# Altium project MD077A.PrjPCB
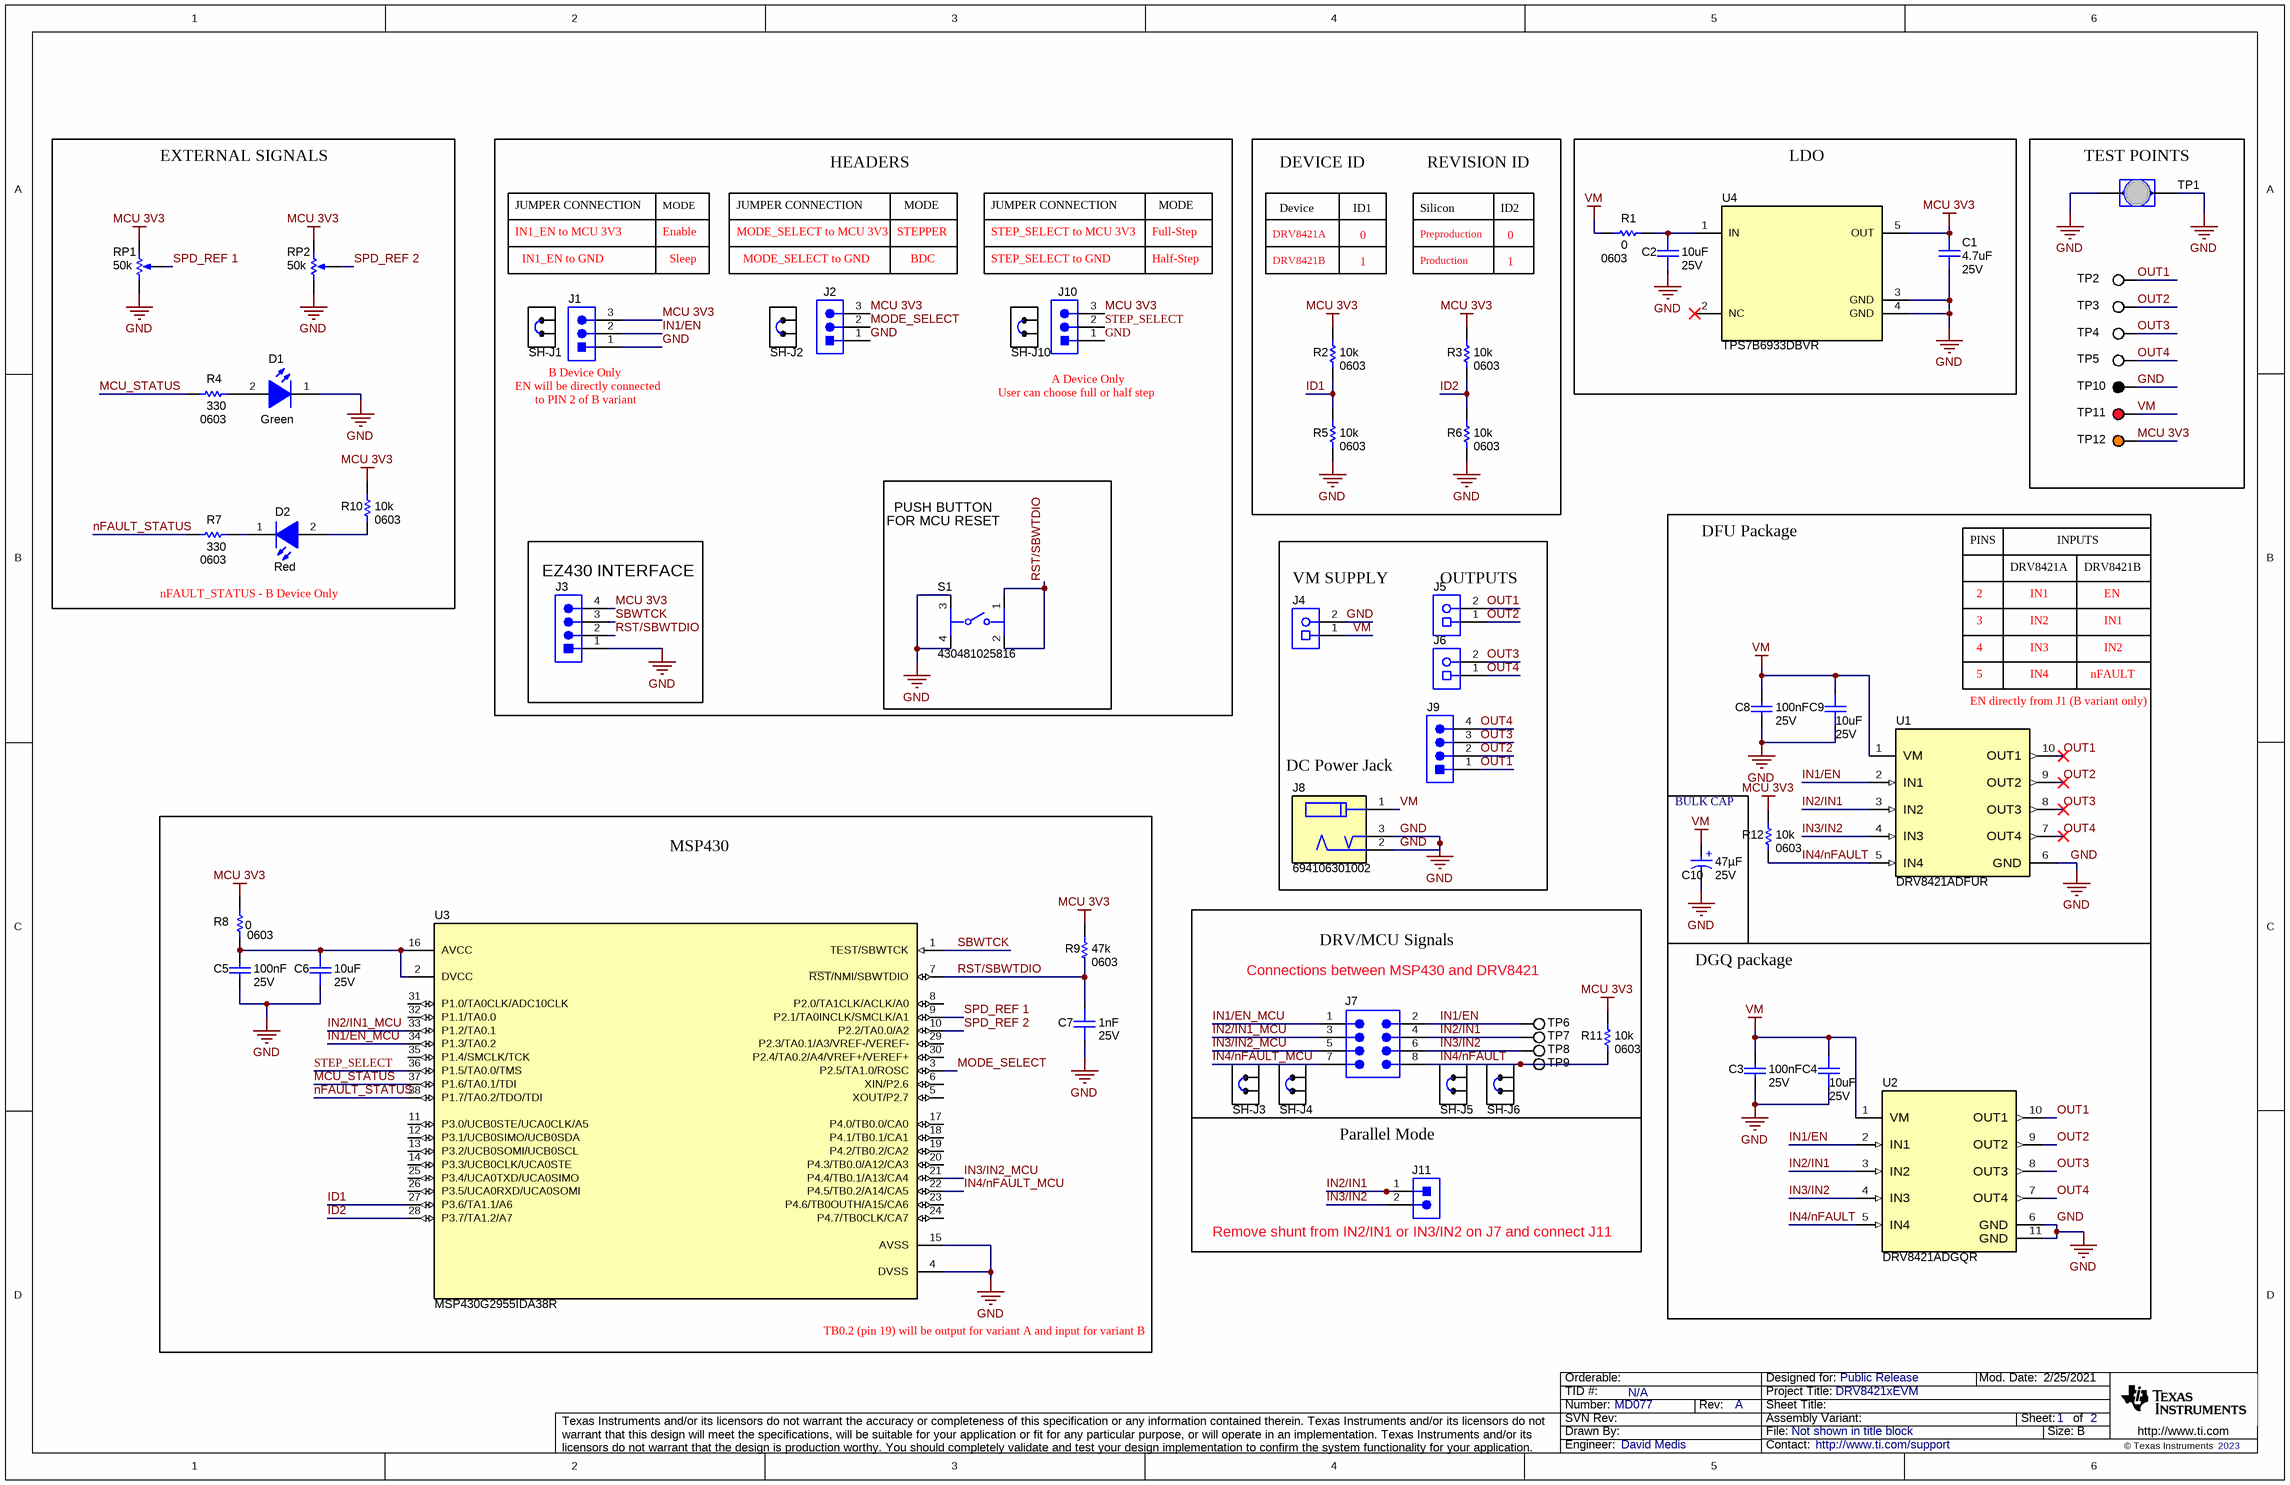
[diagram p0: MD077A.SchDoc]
CopyrightYear: 2023; PCB_Layout: David Medis; PCB_Rev: A; PRJ_Customer: Public Release; PRJ_DrawnBy: David Medis; PRJ_Engineer: David Medis; PRJ_Number: MD077; PRJ_Title: DRV8421xEVM; SCH_Rev: A; TechSupport: http://www.ti.com/support; TID: N/A
2 sheets, 82 parts. Net scope: global (net labels, ports and power ports of the same name join across sheets).
Board file: MD077A.PcbDoc
Sheets:
  MD077A.SchDoc
  MD077A_Hardware.SchDoc

## Sheet MD077A.SchDoc
size 431 x 279 mm; Date: Not shown in title block; ApprovedBy: Not shown in title block; CheckedBy: Not shown in title block; Author: Not shown in title block; CompanyName: Not shown in title block; DrawnBy: David Medis; Engineer: Not shown in title block; Organization: Not shown in title block; Address1: Not shown in title block; Address2: Not shown in title block; Address3: Not shown in title block; Address4: Not shown in title block; DocumentNumber: 1; Revision: Use project parameter SCH_Rev; SheetNumber: 1; SheetTotal: 2; PageSetup: Record=PageOptions¦CenterHorizontal=True¦CenterVertical=True¦PrintScale=1.00¦XCorrection=1.00¦YCorrection=1.00¦PrintKind=0¦BorderSize=5000000¦LeftOffset=0¦BottomOffset=0¦Orientation=2¦PaperLength=1000¦PaperWidth=1000¦Scale=100¦PaperSource=15¦PrintQuality=600¦MediaType=1¦DitherType=10¦PaperKind=Letter¦PrintScaleMode=1

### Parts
C1  ValueDisplayed: 4.7uF  VDC_V: 25V  [FP-GRM188R61E475KE15D_0603-MFG]  (hidden comment: GRM188R61E475KE15D)
C2  ValueDisplayed: 10uF  VDC_V: 25V  [FP-885012106031_0603-MFG]  (hidden comment: 885012106031)
C3  Cap_F: 100nF  VDC_V: 25V  [0603]  (hidden comment: 885012206071)
C4  ValueDisplayed: 10uF  VDC_V: 25V  [FP-885012106031_0603-MFG]  (hidden comment: 885012106031)
C5  Cap_F: 100nF  VDC_V: 25V  [0603]  (hidden comment: 885012206071)
C6  ValueDisplayed: 10uF  VDC_V: 25V  [FP-885012106031_0603-MFG]  (hidden comment: 885012106031)
C7  ValueDisplayed: 1nF  VDC_V: 25V  [FP-885012006044_0603-MFG]  (hidden comment: 885012006044)
C8  Cap_F: 100nF  VDC_V: 25V  [0603]  (hidden comment: 885012206071)
C9  ValueDisplayed: 10uF  VDC_V: 25V  [FP-885012106031_0603-MFG]  (hidden comment: 885012106031)
C10  Cap_F: 47µF  Rated Voltage (DC): 25V  [WCAP-ASLI_D6.3H5.5]  (hidden comment: 865080443007)
D1  value Green  [WL-SMCW_GREEN]  (hidden comment: 150060VS75000)
D2  value Red  [WL-SMCW_RED]  (hidden comment: 150060RS75000)
J1  61300311121  [WURTH_61300311121]  (value not drawn)
J2  61300311121  [WURTH_61300311121]  (value not drawn)
J3  61300411121  [WURTH_61300411121]  (value not drawn)
J4  691101710002  [Wurth_691101710002]  (value not drawn)
J5  691101710002  [Wurth_691101710002]  (value not drawn)
J6  691101710002  [Wurth_691101710002]  (value not drawn)
J7  61300821121  [61300821121]  (value not drawn)
J8  694106301002  [Wurth_694106301002]
J9  61300411121  [WURTH_61300411121]  (value not drawn)
J10  61300311121  [WURTH_61300311121]  (value not drawn)
J11  61300211121  [WURTH_61300211121]  (value not drawn)
R1  PackageReference: 0603  ValueDisplayed: 0  [0603L]  (hidden comment: ERJ-3GEY0R00V)
R2  PackageReference: 0603  ValueDisplayed: 10k  [0603L]  (hidden comment: RC0603JR-0710KL)
R3  PackageReference: 0603  ValueDisplayed: 10k  [0603L]  (hidden comment: RC0603JR-0710KL)
R4  ValueDisplayed: 330  [0603]  (hidden comment: RC0603JR-07330RL)
R5  PackageReference: 0603  ValueDisplayed: 10k  [0603L]  (hidden comment: RC0603JR-0710KL)
R6  PackageReference: 0603  ValueDisplayed: 10k  [0603L]  (hidden comment: RC0603JR-0710KL)
R7  ValueDisplayed: 330  [0603]  (hidden comment: RC0603JR-07330RL)
R8  PackageReference: 0603  ValueDisplayed: 0  [0603L]  (hidden comment: ERJ-3GEY0R00V)
R9  PackageReference: 0603  ValueDisplayed: 47k  [0603L]  (hidden comment: CRCW060347K0JNEA)
R10  PackageReference: 0603  ValueDisplayed: 10k  [0603L]  (hidden comment: RC0603JR-0710KL)
R11  PackageReference: 0603  ValueDisplayed: 10k  [0603L]  (hidden comment: RC0603JR-0710KL)
R12  PackageReference: 0603  ValueDisplayed: 10k  [0603L]  (hidden comment: RC0603JR-0710KL)
RP1  value 50k  [Bourns_3352T]  (hidden comment: 3352T-1-503LF)
RP2  value 50k  [Bourns_3352T]  (hidden comment: 3352T-1-503LF)
S1  430481025816  [FP-430481025816_SMT_SW_6MM2_6MM2-MFG]
SH-J1  60900213421  [Wurth_60900213421]  (value not drawn)
SH-J2  60900213421  [Wurth_60900213421]  (value not drawn)
SH-J3  60900213421  [Wurth_60900213421]  (value not drawn)
SH-J4  60900213421  [Wurth_60900213421]  (value not drawn)
SH-J5  60900213421  [Wurth_60900213421]  (value not drawn)
SH-J6  60900213421  [Wurth_60900213421]  (value not drawn)
SH-J10  60900213421  [Wurth_60900213421]  (value not drawn)
TP1  Jumper_2p  [Harwin_D3082-05]  (value not drawn)
TP2  5012  [Keystone5012]  (value not drawn)
TP3  5012  [Keystone5012]  (value not drawn)
TP4  5012  [Keystone5012]  (value not drawn)
TP5  5012  [Keystone5012]  (value not drawn)
TP6  5002  [Keystone5002]  (value not drawn)
TP7  5002  [Keystone5002]  (value not drawn)
TP8  5002  [Keystone5002]  (value not drawn)
TP9  5002  [Keystone5002]  (value not drawn)
TP10  5011  [Keystone5011]  (value not drawn)
TP11  5010  [Keystone5010]  (value not drawn)
TP12  5013  [Keystone5013]  (value not drawn)
U1  DRV8421ADFUR  [0-IPC_C]
U2  DRV8421ADGQR  [DGQ0010A-MFG]
U3  MSP430G2955IDA38R  [DA0038A_L]
U4  TPS7B6933DBVR  [DBV0005A_N]

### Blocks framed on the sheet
EXTERNAL SIGNALS: D1 D2 R4 R7 R10 RP1 RP2
LDO: C1 C2 R1 U4
TEST POINTS: TP1-TP5 TP10-TP12
DFU Package: C8-C10 R12 U1
MSP430: C5-C7 R8 R9 U3
DRV/MCU Signals: J7 R11 SH-J3-SH-J6 TP6-TP9
DGQ package: C3 C4 U2
Parallel Mode: J11

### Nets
GND: C1.1 C2.1 C3.2 C4.1 C5.2 C6.1 C7.1 C8.2 C9.1 C10.2(N) D1.1(K) J1.1 J2.1 J3.1 J4.2 J8.2 J8.3 J10.1 R5.2 R6.2 RP1.1(CCW) RP2.1(CCW) S1.3 S1.4 TP1.1 TP1.2 TP10.1 U1.6(GND) U2.6(GND) U2.11(GND) U3.4(DVSS) U3.15(AVSS) U4.3(GND) U4.4(GND)
MCU 3V3: C1.2 J1.3 J2.3 J3.4 J10.3 R2.1 R3.1 R8.2 R9.1 R10.1 R11.1 R12.1 RP1.3(CW) RP2.3(CW) TP12.1 U4.5(OUT)
VM: C3.1 C4.2 C8.1 C9.2 C10.1(P) J4.1 J8.1 R1.2 TP11.1 U1.1(VM) U2.1(VM)
ID1: R2.2 R5.1 U3.27(P3.6/TA1.1/A6)
ID2: R3.2 R6.1 U3.28(P3.7/TA1.2/A7)
IN1/EN: J1.2 J7.2 TP6.1 U1.2(IN1) U2.2(IN1)
IN1/EN_MCU: J7.1 U3.34(P1.3/TA0.2)
IN2/IN1: J7.4 J11.1 TP7.1 U1.3(IN2) U2.3(IN2)
IN2/IN1_MCU: J7.3 U3.33(P1.2/TA0.1)
IN3/IN2: J7.6 J11.2 TP8.1 U1.4(IN3) U2.4(IN3)
IN3/IN2_MCU: J7.5 U3.21(P4.4/TB0.1/A13/CA4)
IN4/nFAULT: J7.8 R11.2 R12.2 TP9.1 U1.5(IN4) U2.5(IN4)
IN4/nFAULT_MCU: J7.7 U3.22(P4.5/TB0.2/A14/CA5)
MCU_STATUS: R4.1 U3.37(P1.6/TA0.1/TDI)
MODE_SELECT: J2.2 U3.3(P2.5/TA1.0/ROSC)
nFAULT_STATUS: R7.1 U3.38(P1.7/TA0.2/TDO/TDI)
OUT1: J5.2 J9.1 TP2.1 U1.10(OUT1) U2.10(OUT1)
OUT2: J5.1 J9.2 TP3.1 U1.9(OUT2) U2.9(OUT2)
OUT3: J6.2 J9.3 TP4.1 U1.8(OUT3) U2.8(OUT3)
OUT4: J6.1 J9.4 TP5.1 U1.7(OUT4) U2.7(OUT4)
RST/SBWTDIO: C7.2 J3.2 R9.2 S1.1 S1.2 U3.7(~{RST}/NMI/SBWTDIO)
SBWTCK: J3.3 U3.1(TEST/SBWTCK)
SPD_REF 1: RP1.2(WIPER) U3.9(P2.1/TA0INCLK/SMCLK/A1)
SPD_REF 2: RP2.2(WIPER) U3.10(P2.2/TA0.0/A2)
STEP_SELECT: J10.2 U3.36(P1.5/TA0.0/TMS)
NetC2_2: C2.2 R1.1 U4.1(IN)
NetC5_1: C5.1 C6.2 R8.1 U3.2(DVCC) U3.16(AVCC)
NetD1_2: D1.2(A) R4.2
NetD2_1: D2.1(K) R7.2
NetD2_2: D2.2(A) R10.2

Not connected (* = marked no-connect by the designer): U3 5(XOUT/P2.7) 6(XIN/P2.6) 8(P2.0/TA1CLK/ACLK/A0) 11(P3.0/UCB0STE/UCA0CLK/A5) 12(P3.1/UCB0SIMO/UCB0SDA) 13(P3.2/UCB0SOMI/UCB0SCL) 14(P3.3/UCB0CLK/UCA0STE) 17(P4.0/TB0.0/CA0) 18(P4.1/TB0.1/CA1) 19(P4.2/TB0.2/CA2) 20(P4.3/TB0.0/A12/CA3) 23(P4.6/TB0OUTH/A15/CA6) 24(P4.7/TB0CLK/CA7) 25(P3.4/UCA0TXD/UCA0SIMO) 26(P3.5/UCA0RXD/UCA0SOMI) 29(P2.3/TA0.1/A3/VREF-/VEREF-) 30(P2.4/TA0.2/A4/VREF+/VEREF+) 31(P1.0/TA0CLK/ADC10CLK) 32(P1.1/TA0.0) 35(P1.4/SMCLK/TCK); U4 2(NC)*

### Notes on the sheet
- HEADERS
- DEVICE ID
- REVISION ID
- JUMPER CONNECTION
- MODE
- Device
- ID1
- Silicon
- ID2
- IN1_EN to MCU 3V3
- IN1_EN to GND
- Enable
- Sleep
- MODE_SELECT to MCU 3V3
- MODE_SELECT to GND
- STEPPER
- BDC
- STEP_SELECT to MCU 3V3
- STEP_SELECT to GND
- Full-Step
- Half-Step
- DRV8421A
- DRV8421B
- 0
- 1
- Preproduction
- Production
- (near J1) EN will be directly connected
- to PIN 2 of B variant
- (near J1) B Device Only
- User can choose full or half step
- (near J10) A Device Only
- PUSH BUTTON
- FOR MCU RESET
- PINS
- INPUTS
- nFAULT_STATUS - B Device Only
- (near J3) EZ430 INTERFACE
- (near J4) VM SUPPLY
- (near J5) OUTPUTS
- 2
- 3
- IN1
- IN2
- EN
- (near U1) EN directly from J1 (B variant only)
- 5
- 4
- IN3
- IN4
- nFAULT
- (near J8) DC Power Jack
- BULK CAP
- Connections between MSP430 and DRV8421
- (near J11) Remove shunt from IN2/IN1 or IN3/IN2 on J7 and connect J11
- TB0.2 (pin 19) will be output for variant A and input for variant B

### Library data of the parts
C1 = CMP-0091702-1: 4.7µF ±10% 25V Ceramic Capacitor X5R 0603 (1608 Metric); Manufacturer: Murata; AEC Qualified: No; SizeZ_mm: 1mm; TempCo: 15%
C2 C4 C6 C9 = CMP-0096736-1: 10 µF ±20% 25V Ceramic Capacitor X5R 0603 (1608 Metric); Manufacturer: Wurth; Cap_F: 10µF; AEC Qualified: No; SizeZ_mm: 1mm; Value: 10µF; TempCo: 15%
C3 C5 C8 = CMP-0006832-5: CAP, CERM, 0.1 uF, 25 V, +/- 10%, X7R, 0603; Manufacturer: Wurth Elektronik; TaMin_C: -55°C; Polarized: N; SizeAreaWB_mm2: 4.68; Value1: Unknown; U/M: EA; Value: 0.1uF; TaMax_C: 125°C; SizeZ_mm: 1; SizeX_mm: 1.6; SizeY_mm: 0.8; SizeArea_mm2: 1.28; AEC Category: Q200
C7 = CMP-0097310-1: 1000 pF ±5% 25V Ceramic Capacitor C0G, NP0 0603 (1608 Metric); Manufacturer: Wurth Electronics; Value: 1nF; AEC Qualified: No; TempCo: 30ppm/°C; SizeZ_mm: 0.87mm
C10 = CMP-0107003-1: WCAP-ASLI Aluminum Electrolytic Capacitor, V-Chip, D6.3 x H5.5mm, 47uF, 25V; Manufacturer: Wurth Elektronik; Capacitance Tolerance: +/-20%; Dissipation Factor: 14%; Endurance: 2000h; Leakage Current: 11.75uA; Ripple Current: 220mA; Technical Reference: ASED055470M025DVCTBB000
D1 = CMP-0002894-2: LED, Green, SMD; Manufacturer: Wurth Elektronik; Type: AlInGaP; Value2: 2V; Io_A: 20mA; Value1: W
D2 = CMP-0002947-3: LED, Red, SMD; Manufacturer: Wurth Elektronik; Value1: 0.072W; Vf_V: 2V; Angle: 140; Tjmax_C: 85°C; Type: AlInGaP; Vr_V: 5V; Io_A: 30mA; Power_TotalModule: 72mW
J1 = CMP-0054796-4: Header, 2.54 mm, 3x1, Gold, TH; Manufacturer: Wurth Elektronik; Green_REACh: Passed; CT: FALSE; CNHeader: TRUE; Green_Lifecycle: Active
J2 J10 = CMP-0054796-4: Header, 2.54 mm, 3x1, Gold, TH; Manufacturer: Wurth Elektronik; Green_Lifecycle: Active; Green_REACh: Passed; CT: FALSE; CNHeader: TRUE
J3 J9 = CMP-0054798-2: Header, 2.54 mm, 4x1, Gold, TH; Manufacturer: Wurth Elektronik; Pitch_mm: 2.54; Gender: Male; Row_Count: 1; Cert_UL: Y; Shrouded: N
J4-J6 = CMP-0054828-1: Terminal Block, 5 mm, 2x1, Tin, TH; Manufacturer: Wurth Elektronik; CNHeader: FALSE; Green_Lifecycle: Active; Green_REACh: Passed; CT: TRUE
J7 = CMP-1502-01078-2: CONN HEADER VERT 8POS 2.54MM; NexarPartId: 32855534; Manufacturer: Wurth Electronics; Operating Supply Voltage: 250V; Contact Resistance: 20mΩ; Number of Contacts: 8; Current Rating: 3A; Connector Type: Male Pin; Gender: Male
J8 = CMP-0054778-4: WR-DC DC Power Jack, R/A, TH; Manufacturer: Wurth Elektronik; Gender: Male
J11 = CMP-0054794-2: Header, 2.54 mm, 2x1, Gold, TH; Manufacturer: Wurth Elektronik; Shrouded: N; Gender: Male; Green_REACh: Passed; Pitch_mm: 2.54; Green_Lifecycle: Active; Row_Count: 1; Cert_UL: Y
R1 R8 = CMP-0025874-4: RES, 0, 5%, 0.1 W, AEC-Q200 Grade 0, 0603; Manufacturer: Panasonic; Value: 0; Value_Code: 0000; Power_W: 100mW; Value2: 0.1W; VDC_V: 50V; TempCo: 600 ppm/C; EIA_Code: E24; SizeArea_mm2: 1.28; SizeX_mm: 1.6; SizeY_mm: 0.8; SizeZ_mm: 1; AEC Category: Q200; AEC Qualified: Y; SizeAreaWB_mm2: 4.68
R2 R3 R5 R6 R10-R12 = CMP-0025886-5: RES, 10 k, 5%, 0.1 W, 0603; Manufacturer: Yageo; Power_W: 100mW; TempCo: 100 ppm/C; Value_Code: 10k0; Value: 10k; EIA_Code: E24; SizeX_mm: 1.6; SizeY_mm: 0.8; SizeZ_mm: 1; Value2: 0.1W; SizeArea_mm2: 1.28; AEC Qualified: N; VDC_V: 75V; AEC Category: Q200; SizeAreaWB_mm2: 4.68
R4 R7 = CMP-0025912-5: RES, 330, 5%, 0.1 W, 0603; Manufacturer: Yageo; Power_W: 100mW; TempCo: 100 ppm/C; Value_Code: 330R; Value: 330; EIA_Code: E24; SizeX_mm: 1.6; SizeY_mm: 0.8; SizeZ_mm: 1; Value2: 0.1W; SizeArea_mm2: 1.28; AEC Qualified: N; VDC_V: 75V; AEC Category: Q200; SizeAreaWB_mm2: 4.68
R9 = CMP-0025814-4: RES, 47 k, 5%, 0.1 W, AEC-Q200 Grade 0, 0603; Manufacturer: Vishay-Dale; Value: 47k; Value_Code: 47k0; Power_W: 100mW; Value2: 0.1W; VDC_V: 75V; TempCo: 200 ppm/C; EIA_Code: E24; AEC Category: Q200; AEC Grade: 0; AEC Qualified: Y; SizeArea_mm2: 1.28; SizeX_mm: 1.6; SizeY_mm: 0.8; SizeZ_mm: 1
RP1 RP2 = CMP-0001777-2: Trimming Potentiometer, 50K, 0.5W, TH; Manufacturer: Bourns; CompType: Trimmer
S1 = CMP-0097347-1: Tactile Switch SPST-NO Top Actuated Surface Mount; Manufacturer: Wurth Electronics; VDC_V: 12V; Electromechanical Life: 1000000Cycles; SizeZ_mm: 2.7mm; Coil Resistance_ohm: 100mΩ; Operating Force: 160gf; AEC Qualified: No; Contact Current Rating: 50mA
SH-J1-SH-J6 SH-J10 = CMP-0003761-2: Shunt, 2.54mm, Gold, Black; Manufacturer: Wurth Elektronik
TP1 = CMP-0075110-1: 1mm Uninsulated Shorting Plug, 10.16mm spacing, TH; Manufacturer: Harwin; PartNumber: D3082-05; CompType: Jumper Wire; CNHeader: False; Green_Lifecycle: Active; Green_REACh: Passed
TP2-TP5 = CMP-0055149-2: Test Point, Multipurpose, White, TH; Manufacturer: Keystone Electronics; ContactFinish: Silver; CT: TRUE; CNHeader: FALSE; Green_Lifecycle: Active; Green_REACh: Passed
TP6-TP9 = CMP-0055139-2: Test Point, Miniature, White, TH; Manufacturer: Keystone Electronics; ContactFinish: Silver; Green_REACh: Passed; CT: TRUE; Green_Lifecycle: Active; CNHeader: FALSE
TP10 = CMP-0055148-2: Test Point, Multipurpose, Black, TH; Manufacturer: Keystone Electronics; CNHeader: FALSE; Green_Lifecycle: Active; Green_REACh: Passed; ContactFinish: Silver; CT: TRUE
TP11 = CMP-0055147-2: Test Point, Multipurpose, Red, TH; Manufacturer: Keystone Electronics; CNHeader: FALSE; Green_Lifecycle: Active; Green_REACh: Passed; ContactFinish: Silver; CT: TRUE
TP12 = CMP-0055150-2: Test Point, Multipurpose, Orange, TH; Manufacturer: Keystone Electronics; CT: TRUE; ContactFinish: Silver; Green_REACh: Passed; CNHeader: FALSE; Green_Lifecycle: Active
U1 = CMP-0065579-1: Dual H-Bridge Stepper Driver, SSOP10; Manufacturer: Texas Instruments; SizeZ_mm: 1.75mm; AEC Qualified: No; Max Supply Voltage: 18V; Min Supply Voltage: 4V; Nominal Supply Current: 3.8mA; Number Of Outputs: 4; Standoff Height: 0.1mm; Switching Frequency: 250kHz; TaMax_C: +85°C; TaMin_C: -40°C; TJmax_C: +150°C
U2 = CMP-0065580-1: Dual H-Bridge Stepper Driver; Manufacturer: Texas Instruments; SizeZ_mm: 1.1mm; AEC Qualified: No; Max Supply Voltage: 18V; Min Supply Voltage: 4V; Nominal Supply Current: 3.8mA; Number Of Outputs: 4; Standoff Height: 0.05mm; Switching Frequency: 250kHz; TaMax_C: +85°C; TaMin_C: -40°C; TJmax_C: +150°C
U3 = CMP-0076631-1: MSP430G2x55 Mixed Signal Microcontroller, DA0038A (TSSOP-38); Manufacturer: Texas Instruments; SizeAreaWB_mm2: 146.45; SizeArea_mm2: 101.25; SizeZ_mm: 1.2; SizeY_mm: 12.5; U/M: EA; CompType: IC; SizeX_mm: 8.1
U4 = CMP-0077328-2: 40-V Ultralow-Iq Low-Dropout Regulator, DBV0005A (SOT-23-5); Manufacturer: Texas Instruments; SizeArea_mm2: 8.12; CompType: IC; SizeAreaWB_mm2: 14.82; SizeY_mm: 2.9; SizeZ_mm: 1.45; SizeX_mm: 2.8; AEC Category: Q200; AEC Qualified: N

## Sheet MD077A_Hardware.SchDoc
size 431 x 279 mm; Date: Not shown in title block; ApprovedBy: Not shown in title block; CheckedBy: Not shown in title block; Author: Not shown in title block; CompanyName: Not shown in title block; DrawnBy: Murugavel Raju; Engineer: Not shown in title block; Organization: Not shown in title block; Address1: Not shown in title block; Address2: Not shown in title block; Address3: Not shown in title block; Address4: Not shown in title block; DocumentNumber: 2; Revision: Use project parameter SCH_Rev; SheetNumber: 2; SheetTotal: 2; PageSetup: Record=PageOptions¦CenterHorizontal=True¦CenterVertical=True¦PrintScale=1.00¦XCorrection=1.00¦YCorrection=1.00¦PrintKind=0¦BorderSize=5000000¦LeftOffset=0¦BottomOffset=0¦Orientation=2¦PaperLength=1000¦PaperWidth=1000¦Scale=100¦PaperSource=15¦PrintQuality=600¦MediaType=1¦DitherType=10¦PaperKind=Letter¦PrintScaleMode=1
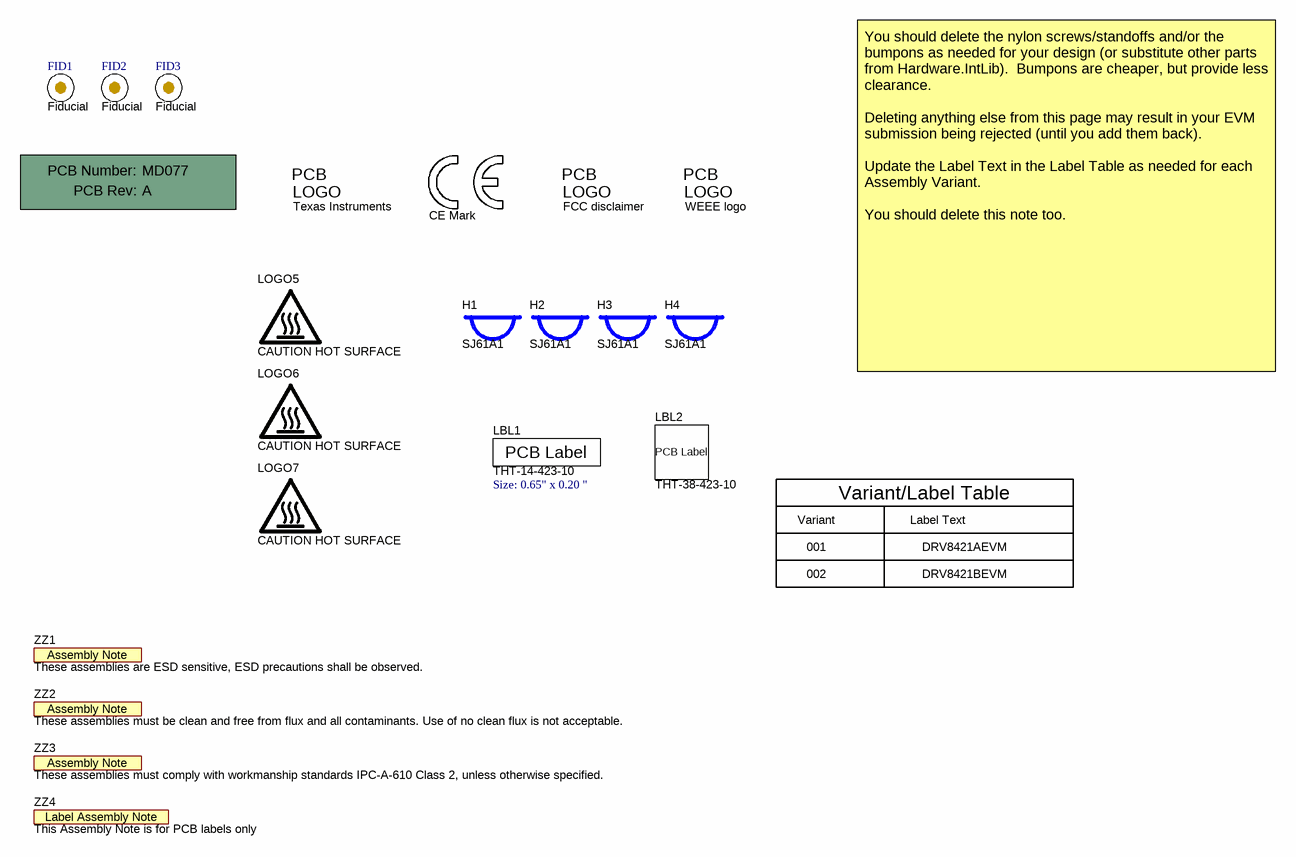
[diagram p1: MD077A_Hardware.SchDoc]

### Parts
!PCB1  Printed Circuit Board  (value not drawn)  (mechanical)
FID1  Fiducial  [Fiducial10-30]  (no BOM)
FID2  Fiducial  [Fiducial10-30]  (no BOM)
FID3  Fiducial  [Fiducial10-30]  (no BOM)
H1  SJ61A1  [Bumpon_SJ61A1]
H2  SJ61A1  [Bumpon_SJ61A1]
H3  SJ61A1  [Bumpon_SJ61A1]
H4  SJ61A1  [Bumpon_SJ61A1]
LBL1  THT-14-423-10  Note: Size: 0.65" x 0.20 "  [Label_650x200]
LBL2  THT-38-423-10  [Label_375x375]
Logo1  Texas Instruments  [TI_Symbol_Overlay_Small]  (no BOM)
Logo2  CE Mark  [CE_Mark_5mm]  (no BOM)
Logo3  FCC disclaimer  [FCC_disclaimer]  (no BOM)
Logo4  WEEE logo  [WEEE_Minimum]  (no BOM)
LOGO5  CAUTION HOT SURFACE  [IEC_HotSurface_Small]  (no BOM)
LOGO6  CAUTION HOT SURFACE  [IEC_HotSurface_Small]  (no BOM)
LOGO7  CAUTION HOT SURFACE  [IEC_HotSurface_Small]  (no BOM)
ZZ1  These assemblies are ESD sensitive, ESD precautions shall be observed.  [AssemblyNote]  (no BOM)
ZZ2  These assemblies must be clean and free from flux and all contaminants. Use of no clean flux is not acceptable.  [AssemblyNote]  (no BOM)
ZZ3  These assemblies must comply with workmanship standards IPC-A-610 Class 2, unless otherwise specified.  [AssemblyNote]  (no BOM)
ZZ4  This Assembly Note is for PCB labels only  [AssemblyNoteLabel]  (no BOM)

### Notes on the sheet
- You should delete the nylon screws/standoffs and/or the bumpons as needed for your design (or substitute other parts from Hardware.IntLib).  Bumpons are cheaper, but provide less clearance.
  Deleting anything else from this page may result in your EVM submission being rejected (until you add them back).
  Update the Label Text in the Label Table as needed for each Assembly Variant.
  You should delete this note too.
- Variant/Label Table
- Variant
- 001
- Label Text
- DRV8421AEVM
- 002
- DRV8421BEVM

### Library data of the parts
!PCB1 = CMP-0003618-2: Manufacturer: Any; PartNumber: MD077
FID1-FID3 = CMP-0077181-1: Fiducial mark.  There is nothing to buy or mount.
H1-H4 = CMP-0003621-1: Bumpon, Cylindrical, 0.312 X 0.200, Black; Manufacturer: 3M
LBL1 = CMP-0003625-1: Thermal Transfer Printable Labels, 0.650" W x 0.200" H - 10,000 per roll; Manufacturer: Brady
LBL2 = CMP-00007-1: Harsh Environment Multi-Purpose Polyester Labels for 3" Core Printers - 0.375" x 0.375", White; Manufacturer: Brady; PartNumber: THT-14-423-10; Body Material: PET,Polyester; Note: Size: 0.375" x 0.375"
Logo1 = CMP-0074838-1: Texas Instrument Corporate Signature; SymbolCreator: a0412235; Lib Reference: TI_Logo
Logo2 = CMP-0074844-1: SymbolCreator: a0412235
Logo3 = CMP-0074847-1: FCC_disclaimer
Logo4 = CMP-0074769-3: Manufacturer: Texas Instruments; CompType: IC; AEC Category: Q200
LOGO5-LOGO7 = CMP-0074837-2: IEC 61010-1 Hot Surface Warning; Manufacturer: Texas Instruments; SymbolCreator: a0412235; CompType: IC; AEC Category: Q200
ZZ1 = CMP-0077236-1
ZZ2 = CMP-0077237-1
ZZ3 = CMP-0077238-1
ZZ4 = CMP-0003616-3

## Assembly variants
001: not fitted J1 R2 R6 SH-J1 U1
002: not fitted R5 R6 R11 R12 U2; alternate parts U? -> CMP-0065583-1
